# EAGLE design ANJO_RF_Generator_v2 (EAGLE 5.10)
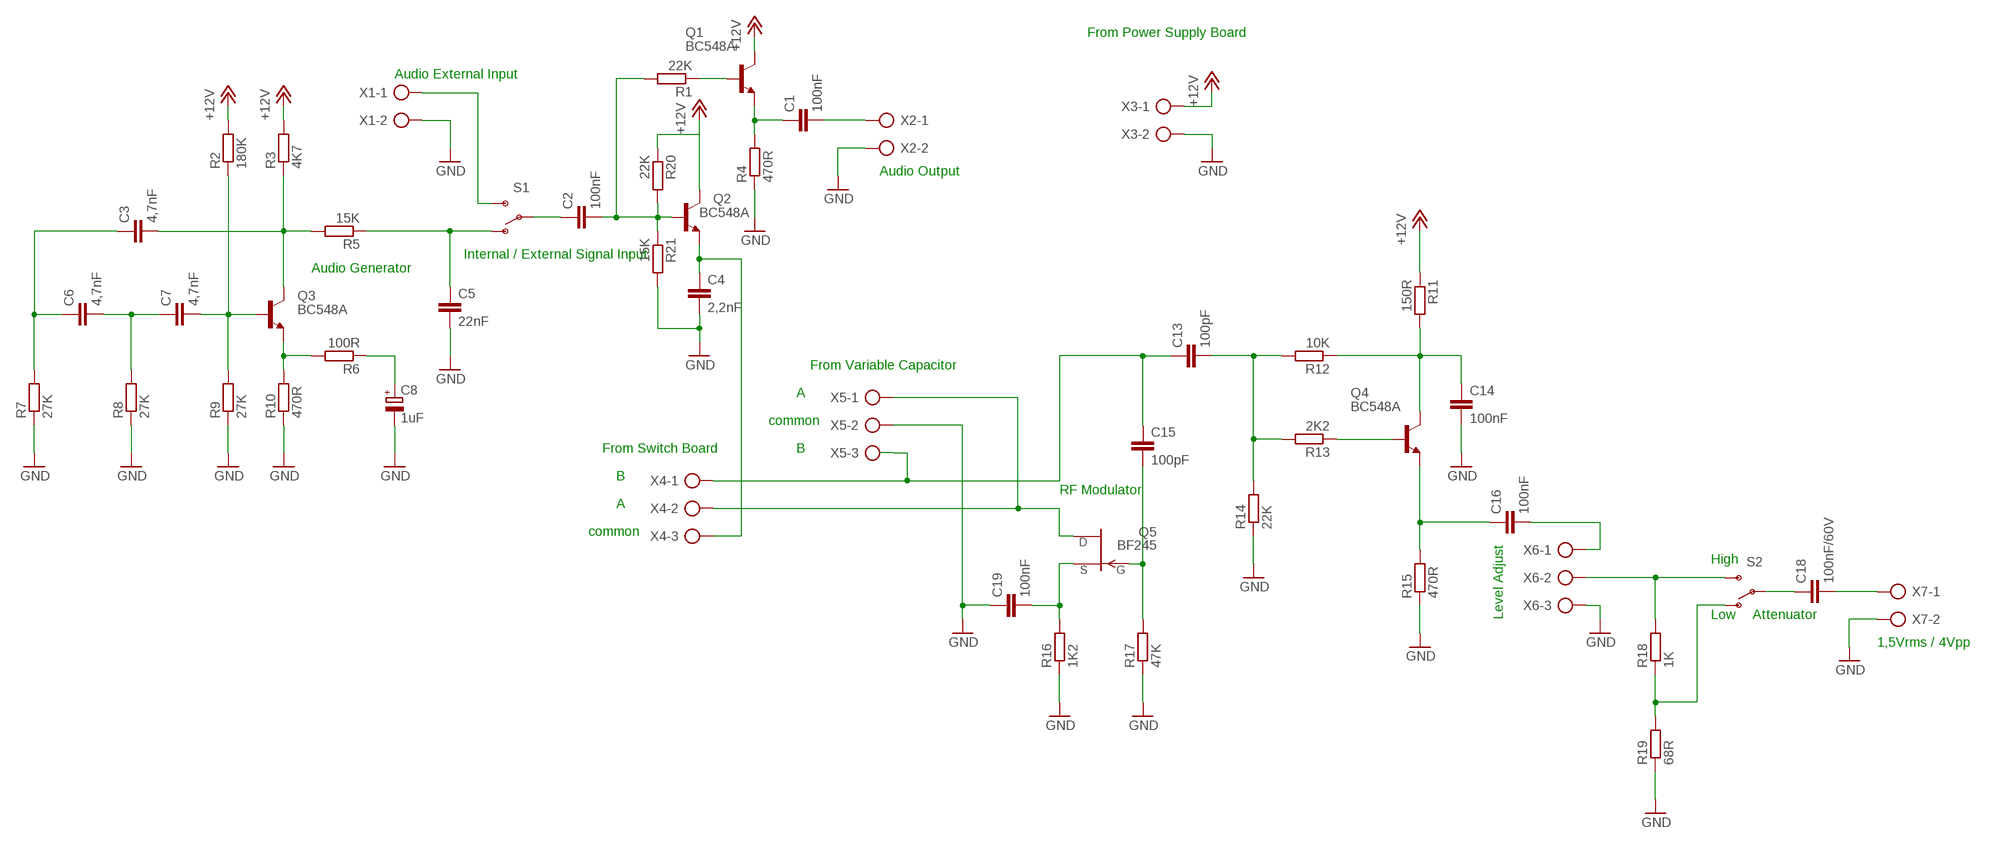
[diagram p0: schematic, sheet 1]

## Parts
C1  100nF  C-EU075-032X103  [C075-032X103]
C2  100nF  C-EU075-032X103  [C075-032X103]
C3  4,7nF  C-EU075-032X103  [C075-032X103]
C4  2,2nF  C-EU075-032X103  [C075-032X103]
C5  22nF  C-EU075-032X103  [C075-032X103]
C6  4,7nF  C-EU075-032X103  [C075-032X103]
C7  4,7nF  C-EU075-032X103  [C075-032X103]
C8  1uF  CPOL-EUE5-6  [E5-6]
C13  100pF  C-EU075-032X103  [C075-032X103]
C14  100nF  C-EU075-032X103  [C075-032X103]
C15  100pF  C-EU075-032X103  [C075-032X103]
C16  100nF  C-EU075-032X103  [C075-032X103]
C18  100nF/60V  C-EU075-032X103  [C075-032X103]
C19  100nF  C-EU075-032X103  [C075-032X103]
Q1  BC548A  [TO92-EBC]
Q2  BC548A  [TO92-EBC]
Q3  BC548A  [TO92-EBC]
Q4  BC548A  [TO92-EBC]
Q5  BF245  [TO92]
R1  22K  R-EU_0207/10  [0207/10]
R2  180K  R-EU_0207/10  [0207/10]
R3  4K7  R-EU_0207/10  [0207/10]
R4  470R  R-EU_0207/10  [0207/10]
R5  15K  R-EU_0207/10  [0207/10]
R6  100R  R-EU_0207/10  [0207/10]
R7  27K  R-EU_0207/10  [0207/10]
R8  27K  R-EU_0207/10  [0207/10]
R9  27K  R-EU_0207/10  [0207/10]
R10  470R  R-EU_0207/10  [0207/10]
R11  150R  R-EU_0207/10  [0207/10]
R12  10K  R-EU_0207/10  [0207/10]
R13  2K2  R-EU_0207/10  [0207/10]
R14  22K  R-EU_0207/10  [0207/10]
R15  470R  R-EU_0207/10  [0207/10]
R16  1K2  R-EU_0207/10  [0207/10]
R17  47K  R-EU_0207/10  [0207/10]
R18  1K  R-EU_0207/10  [0207/10]
R19  68R  R-EU_0207/10  [0207/10]
R20  22K  R-EU_0207/10  [0207/10]
R21  15K  R-EU_0207/10  [0207/10]
S1  SWITCH-SPSTPTH  [SWITCH-SPDT]
S2  SWITCH-SPSTPTH  [SWITCH-SPDT]
X1  AK300/2  [AK300/2]
X2  AK300/2  [AK300/2]
X3  AK300/2  [AK300/2]
X4  AK300/3  [AK300/3]
X5  AK300/3  [AK300/3]
X6  AK300/3  [AK300/3]
X7  AK300/2  [AK300/2]

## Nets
+12V: Q1.C Q2.C R2.2 R3.2 R11.1 R20.1 X3.1
GND: C4.2 C5.2 C8.- C14.2 C19.1 R4.1 R7.1 R8.1 R9.1 R10.1 R14.1 R15.1 R16.1 R17.1 R19.1 R21.2 X1.2 X2.2 X3.2 X5.2 X6.3 X7.2
N$1: C3.1 C6.1 R7.2
N$2: C6.2 C7.1 R8.2
N$3: C7.2 Q3.B R2.1 R9.2
N$4: Q3.E R6.2 R10.2
N$5: C8.+ R6.1
N$6: C3.2 Q3.C R3.1 R5.2
N$7: C5.1 R5.1 S1.1(O)
N$8: S1.3(S) X1.1
N$9: C2.1 S1.2(P)
N$10: C2.2 Q2.B R1.2 R20.2 R21.1
N$12: Q1.B R1.1
N$13: C1.1 Q1.E R4.2
N$14: C1.2 X2.1
N$15: C4.1 Q2.E X4.3
N$16: C13.1 C15.1 X4.1 X5.3
N$25: Q4.B R13.1
N$27: C19.2 Q5.2(S) R16.2
N$28: C15.2 Q5.3(G) R17.2
N$29: Q5.1(D) X4.2 X5.1
N$30: C16.2 X6.1
N$31: C18.2 X7.1
N$32: R18.1 R19.2 S2.1(O)
N$35: C18.1 S2.2(P)
N$37: R18.2 S2.3(S) X6.2
N$39: C13.2 R12.2 R13.2 R14.2
N$40: C14.1 Q4.C R11.2 R12.1
N$42: C16.1 Q4.E R15.2

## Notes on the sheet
- From Power Supply Board
- Audio External Input
- Audio Output
- Internal / External Signal Input
- Audio Generator
- From Variable Capacitor
- A
- common
- From Switch Board | B
- B
- RF Modulator
- A
- common
- High
- Level Adjust | Low | Attenuator
- 1,5Vrms / 4Vpp

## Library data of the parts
C1-C7 C13-C16 C18 C19 = resistor:C-EU: CAPACITOR, European symbol
C8 = resistor:CPOL-EU: POLARIZED CAPACITOR, European symbol
Q1-Q4 = transistor-npn:BC548*: NPN Transistor
Q5 = transistor-fet:BF245: N-Channel Junction FET http://www.onsemi.com/pub/Collateral/BF245A-D.PDF
R1-R21 = resistor:R-EU_: RESISTOR, European symbol
S1 S2 = SparkFun:SWITCH-SPST: SPST Switch Simple slide switch. Spark Fun Electronics SKU : COM-00102
X1-X3 X7 = con-ptr500:AK300/2: CONNECTOR
X4-X6 = con-ptr500:AK300/3: CONNECTOR

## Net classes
0 default: width 0.559 mm, drill 0.559 mm, clearance 0.559 mm

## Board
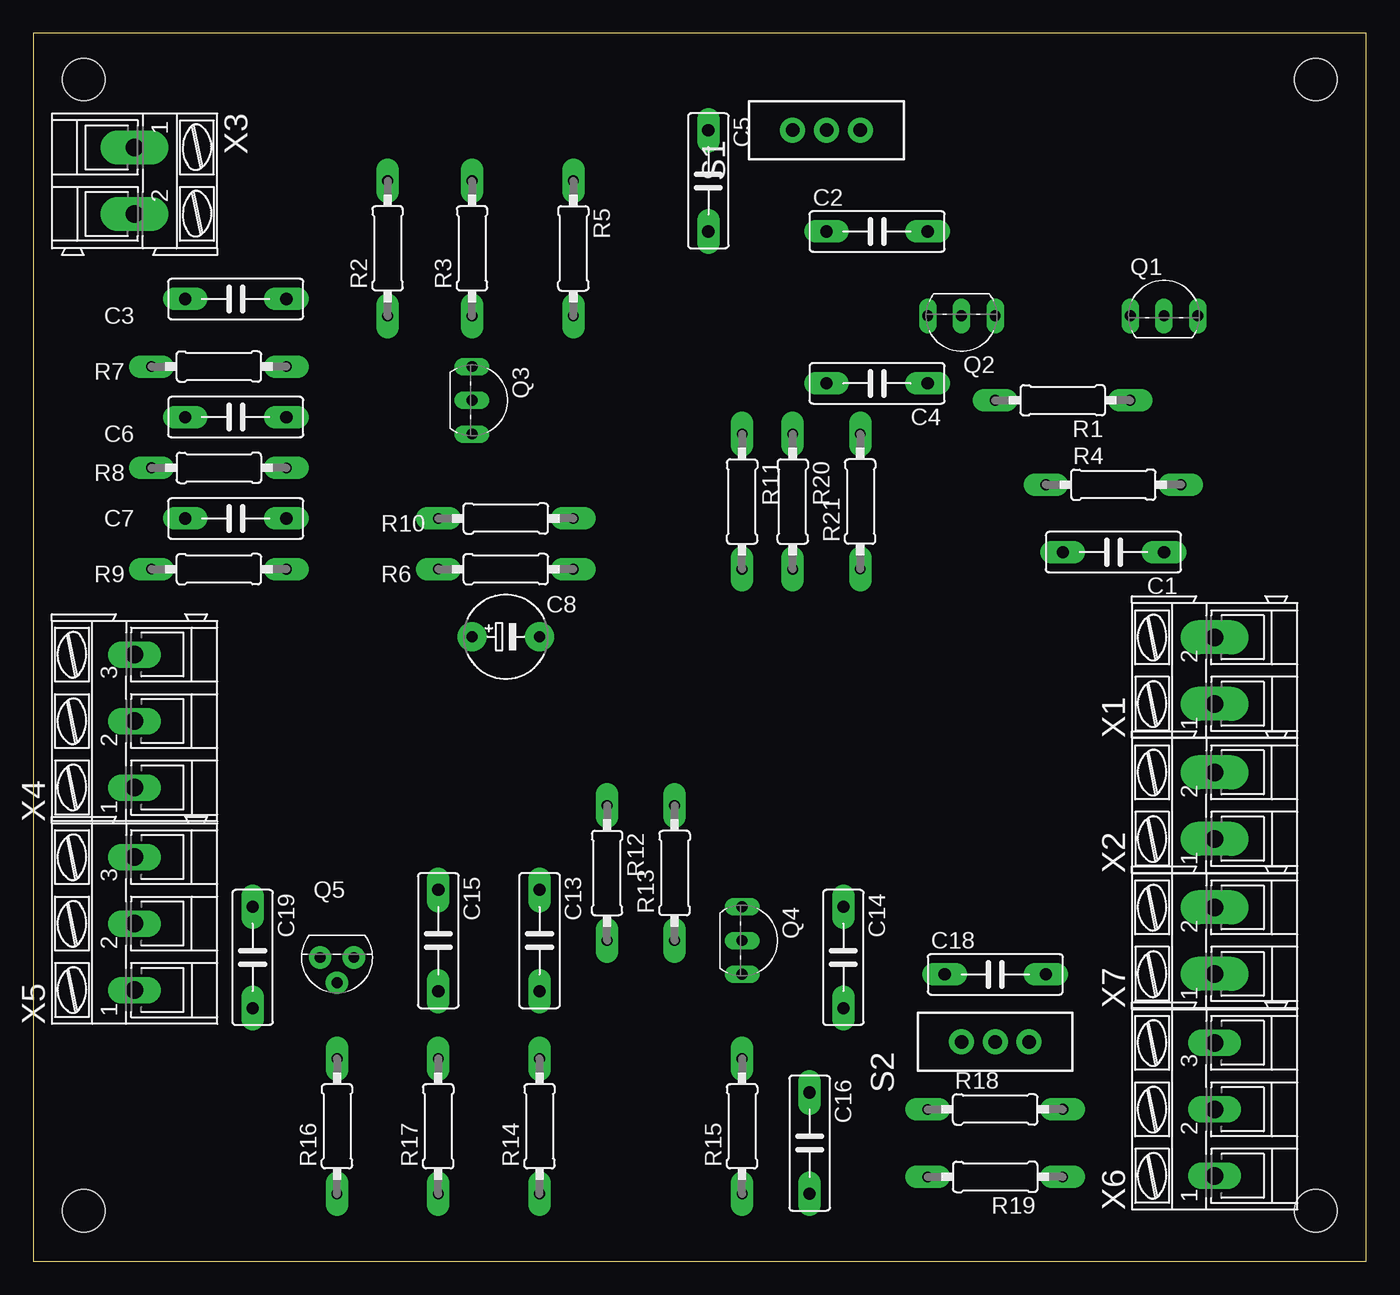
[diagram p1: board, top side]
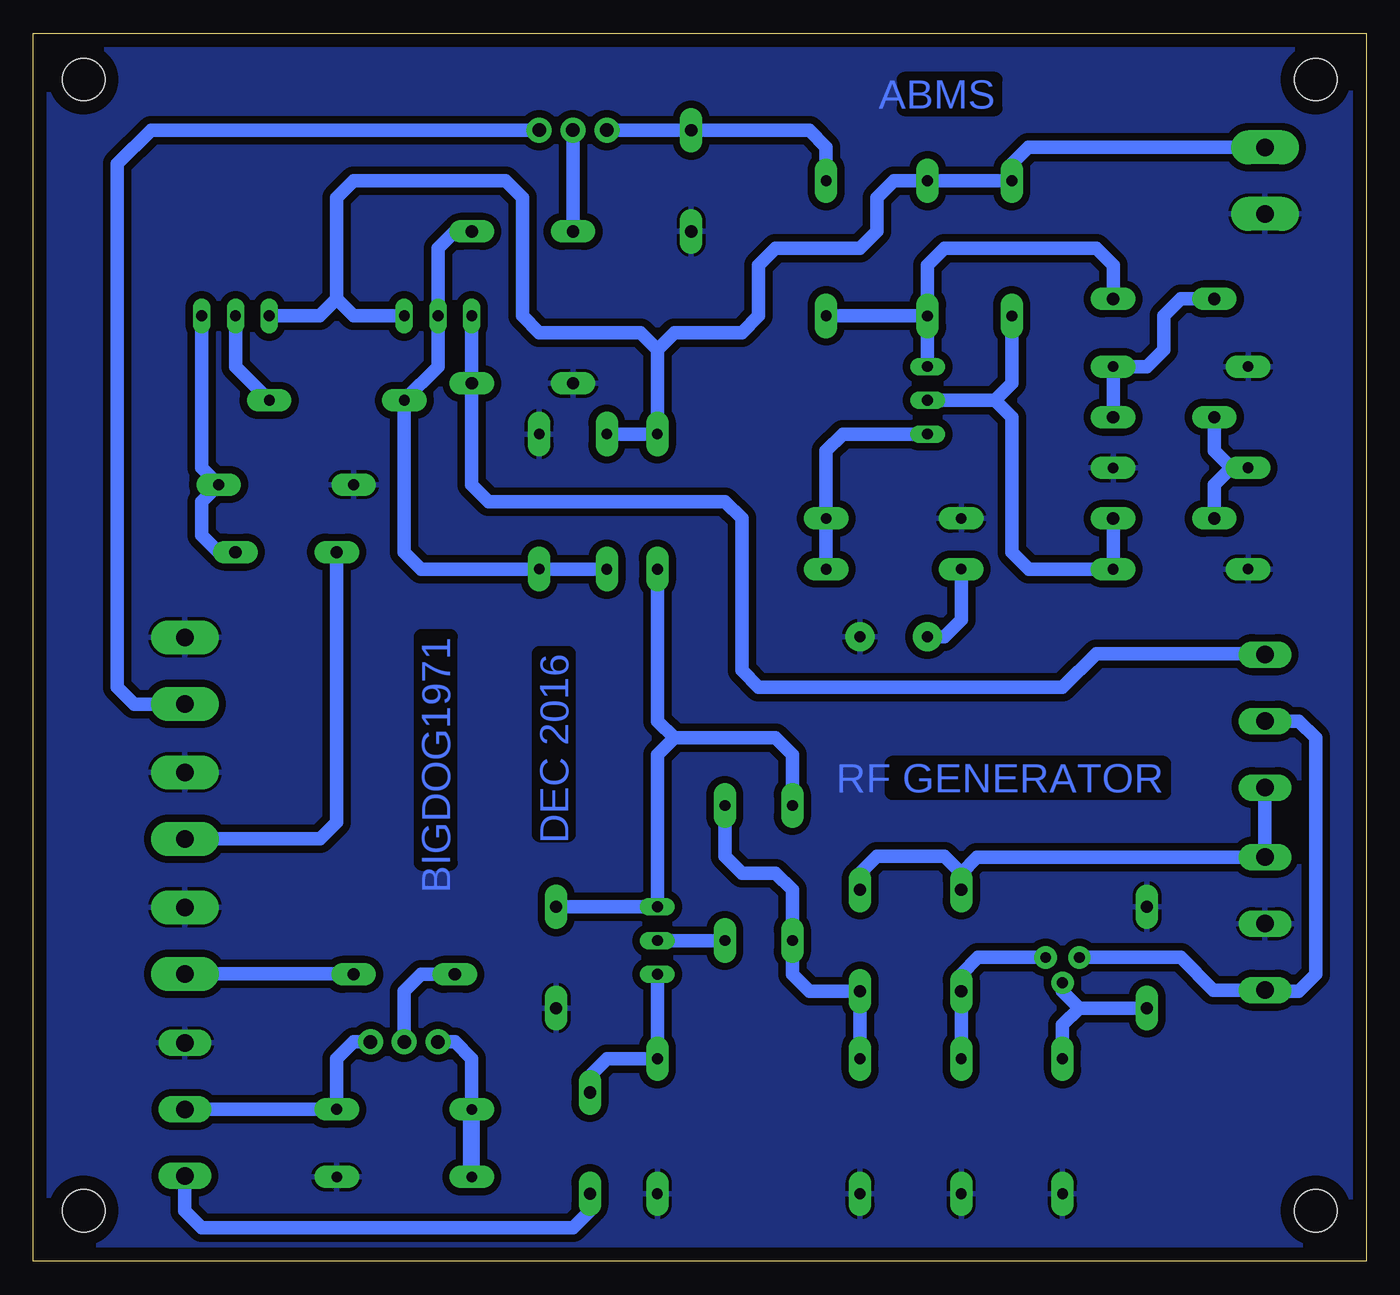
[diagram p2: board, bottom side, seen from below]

Size 100.31 x 92.38 mm. Coordinates in mm from the lower left corner, seen from the top.
Outline: 0,0 100.31,0 100.31,92.38 0,92.38 0,0
Copper layers (1*16): Top 0.035mm / dielectric 1.5mm / Bottom 0.035mm
Design rules "default": minimum track width 10mil, minimum drill 24mil, track to track 8mil, track to pad 8mil, pad to pad 8mil, via to via 8mil, smd to smd 8mil, copper to edge 40mil, drill to drill 8mil, minimum pad ring 10mil, minimum via ring 8mil, stop-mask expansion 4mil, vias tented up to drill 0mil, thermal gap 10mil
Holes 3.2 mm at 3.81,88.9 96.52,88.9 96.52,3.81 3.81,3.81

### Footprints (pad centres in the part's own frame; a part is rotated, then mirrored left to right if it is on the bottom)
C075-032X103 = drill 0.914 pad 1.676 long: 1 -3.81,0; 2 3.81,0
E5-6 = drill 0.813 pad 2.184 round: + -2.54,0; - 2.54,0
TO92-EBC = drill 0.813 long: B 0,-1.27; C -2.54,-1.27; E 2.54,-1.27
TO92 = drill 0.813 pad 1.676 round: 1 1.27,0; 2 0,1.905; 3 -1.27,0
0207/10 = drill 0.8 pad 1.676 long: 1 -5.08,0 | drill 0.813 pad 1.676 long: 2 5.08,0
SWITCH-SPDT = drill 1.016 pad 1.88 round: 1 0,2.54; 2 0,0; 3 0,-2.54
AK300/2 = drill 1.321 pad 2.54 long: 1 -2.515,0; 2 2.489,0
AK300/3 = drill 1.321 long: 1 -5.004,0; 2 0,0; 3 5.004,0

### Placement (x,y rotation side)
C1  81.28,53.34 180 top
C2  63.5,77.47 0 top
C3  15.24,72.39 0 top
C4  63.5,66.04 180 top
C5  50.8,81.28 270 top
C6  15.24,63.5 180 top
C7  15.24,55.88 0 top
C8  35.56,46.99 0 top
C13  38.1,24.13 270 top
C14  60.96,22.86 270 top
C15  30.48,24.13 270 top
C16  58.42,8.89 270 top
C18  72.39,21.59 0 top
C19  16.51,22.86 270 top
Q1  85.09,72.39 0 top
Q2  69.85,69.85 180 top
Q3  34.29,64.77 270 top
Q4  54.61,24.13 270 top
Q5  22.86,22.86 180 top
R1  77.47,64.77 180 top
R2  26.67,76.2 90 top
R3  33.02,76.2 90 top
R4  81.28,58.42 0 top
R5  40.64,76.2 270 top
R6  35.56,52.07 0 top
R7  13.97,67.31 0 top
R8  13.97,59.69 180 top
R9  13.97,52.07 0 top
R10  35.56,55.88 0 top
R11  53.34,57.15 270 top
R12  43.18,29.21 270 top
R13  48.26,29.21 90 top
R14  38.1,10.16 90 top
R15  53.34,10.16 90 top
R16  22.86,10.16 90 top
R17  30.48,10.16 90 top
R18  72.39,11.43 0 top
R19  72.39,6.35 180 top
R20  57.15,57.15 270 top
R21  62.23,57.15 90 top
S1  59.69,85.09 90 top
S2  72.39,16.51 90 top
X1  88.9,44.45 90 top
X2  88.9,34.29 90 top
X3  7.62,81.28 270 top
X4  7.62,40.64 90 top
X5  7.62,25.4 90 top
X6  88.9,11.43 90 top
X7  88.9,24.13 90 top

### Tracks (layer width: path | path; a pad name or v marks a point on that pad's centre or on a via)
+12V
  Bottom 1.016: X3.1 25.43,83.8 26.67,82.55 R2.2 R3.2 35.56,81.28 36.83,80.01 36.83,77.47 38.1,76.2 44.45,76.2 45.72,74.93 45.72,71.12 46.99,69.85 52.07,69.85 53.34,68.58 | Q1.C 78.74,71.12 77.47,72.39 | 77.47,72.39 77.47,80.01 76.2,81.28 64.77,81.28 63.5,80.01 63.5,71.12 62.23,69.85 54.61,69.85 53.34,68.58 | Q2.C 76.2,71.12 77.47,72.39 | 53.34,68.58 R11.1 R20.1
GND
  pour Bottom: -1.27,93.98 101.6,93.98 101.6,-1.27 -1.27,-1.27
N$1
  Bottom 1.016: C6.1 R7.2 16.51,67.31 15.24,68.58 15.24,71.12 13.97,72.39 C3.1
N$2
  Bottom 1.016: C7.1 11.43,58.42 10.16,59.69 | R8.2 10.16,59.69 | 10.16,59.69 11.43,60.96 C6.2
N$3
  Bottom 1.016: C7.2 R9.2 25.4,52.07 26.67,53.34 26.67,63.5 27.94,64.77 | R2.1 26.67,66.04 27.94,64.77 | 27.94,64.77 Q3.B
N$4
  Bottom 1.016: Q3.E 39.37,62.23 40.64,60.96 R10.2 R6.2
N$5
  Bottom 1.016: R6.1 30.48,48.26 31.75,46.99 C8.+
N$6
  Bottom 1.016: R3.1 R5.2 | R3.1 Q3.C | C3.2 19.05,74.93 20.32,76.2 31.75,76.2 33.02,74.93 R3.1
N$7
  Bottom 1.016: S1.1 C5.1 41.91,85.09 40.64,83.82 R5.1
N$8
  Bottom 1.016: S1.3 91.44,85.09 93.98,82.55 93.98,43.18 92.71,41.91 88.92,41.91 X1.1
N$9
  Bottom 1.016: C2.1 S1.2
N$10
  Bottom 1.016: C2.2 68.58,77.47 69.85,76.2 Q2.B 69.85,67.31 R1.2 72.39,53.34 71.12,52.07 R21.1 R20.2
N$12
  Bottom 1.016: R1.1 85.09,67.31 Q1.B
N$13
  Bottom 1.016: Q1.E 87.63,59.69 R4.2 87.63,57.15 87.63,54.61 86.36,53.34 C1.1
N$14
  Bottom 1.016: X2.1 78.72,31.77 77.47,33.02 C1.2
N$15
  Bottom 1.016: Q2.E C4.1 67.31,58.42 66.04,57.15 48.26,57.15 46.99,55.88 46.99,44.45 45.72,43.18 22.86,43.18 20.32,45.72 7.7,45.72 X4.3
N$16
  Bottom 1.016: 30.48,29.21 29.29,30.4 X5.3 X4.1 | 30.48,29.21 C15.1 | 30.48,29.21 31.75,30.48 36.83,30.48 38.1,29.21 C13.1
N$25
  Bottom 1.016: R13.1 Q4.B
N$27
  Bottom 1.016: R16.2 22.86,17.78 21.59,19.05 | C19.2 21.59,19.05 | Q5.2 22.86,20.32 21.59,19.05
N$28
  Bottom 1.016: R17.2 C15.2 30.48,21.59 29.21,22.86 Q5.3
N$29
  Bottom 1.016: Q5.1 13.97,22.86 11.51,20.4 X5.1 7.54,20.32 5.08,20.32 3.81,21.59 3.81,39.37 5.08,40.64 X4.2
N$30
  Bottom 1.016: C16.2 58.42,3.81 59.69,2.54 87.63,2.54 88.9,3.81 X6.1
N$31
  Bottom 1.016: X7.1 76.22,21.61 C18.2
N$32
  Bottom 1.016: S2.1 68.58,16.51 67.31,15.24 R18.1
  Bottom 1.27: R19.2 R18.1
N$35
  Bottom 1.016: S2.2 72.39,20.32 71.12,21.59 C18.1
N$37
  Bottom 1.016: X6.2 R18.2 77.47,15.24 76.2,16.51 S2.3
N$39
  Bottom 1.016: R14.2 C13.2 41.91,20.32 43.18,21.59 R12.2 43.18,27.94 44.45,29.21 46.99,29.21 48.26,30.48 R13.2
N$40
  Bottom 1.016: R12.1 43.18,38.1 44.45,39.37 52.07,39.37 | 52.07,39.37 53.34,38.1 Q4.C C14.1 | R11.2 53.34,40.64 52.07,39.37
N$42
  Bottom 1.016: Q4.E R15.2 57.15,15.24 58.42,13.97 C16.1

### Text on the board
Bottom: ABMS | BIGDOG1971 | DEC 2016 | RF GENERATOR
